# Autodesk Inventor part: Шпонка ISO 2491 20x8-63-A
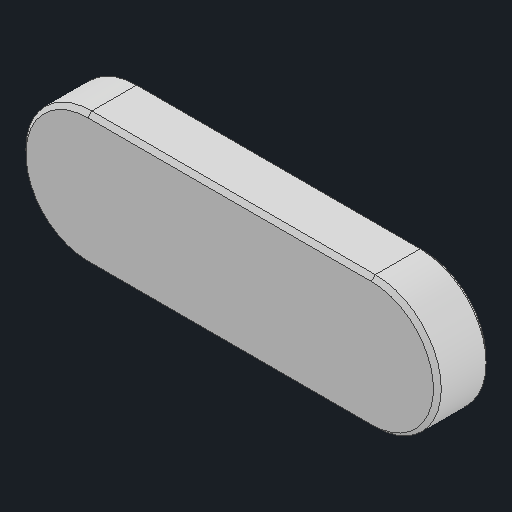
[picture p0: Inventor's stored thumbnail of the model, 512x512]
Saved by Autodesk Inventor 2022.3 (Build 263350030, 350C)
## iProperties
Created: 2020-09
Part Number: Шпонка ISO 2491 20x8-63-A
Material: Типовые
Document SubType Name: Modeling
Designer: Карташов
Density: 1 g/cm^3
Appearance: По умолчанию
Title: D:\мои документы\Ирина\_WorldSkills\2020_09 ФНЧ\Module A\Участникам\GIVEN\Шпонка ISO 2491 20x8-63-A.stp
Author: Дом
Sending System: Autodesk Inventor 2021
Preprocessor: ST-DEVELOPER v18.1
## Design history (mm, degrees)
feature "Твердое тело2"
node "Твердое тело1"
